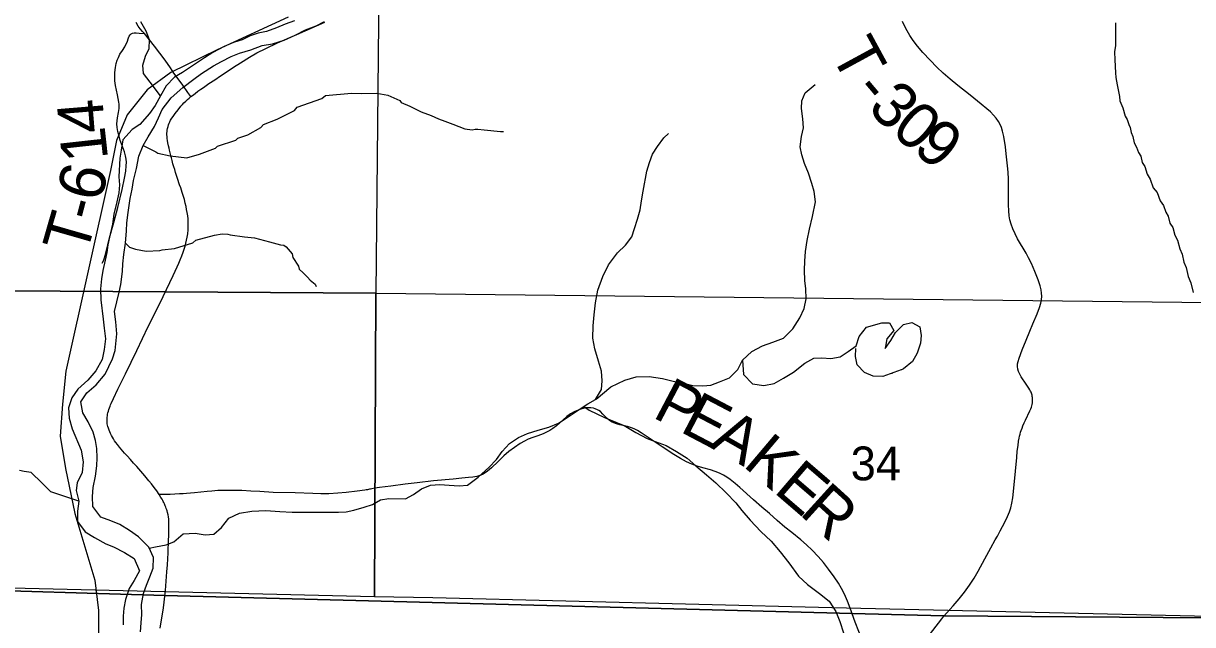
# Model space of a CAD drawing. Extents: x 0 to 34, y -8.9 to 22.
# Drawn here: x 24.652 to 26.101, y 15.928 to 16.673 of the extents above; entities that cross this region are included whole.
import ezdxf

# ---------------------------------------------------------------- set-up
doc = ezdxf.new("R2010")
doc.units = 0
for name, color, linetype in [('GM_X_Corporation', 7, 'Continuous'), ('GM_X_Major_River', 7, 'Continuous'), ('GM_X_Minor_River', 7, 'Continuous'), ('GM_X_Rail_Line', 7, 'Continuous'), ('GM_X_Section_Text', 7, 'Continuous'), ('GM_X_State_Route', 7, 'Continuous'), ('GM_X_Township_Road', 7, 'Continuous'), ('GM_X_Township_Road_Text', 7, 'Continuous')]:
    doc.layers.add(name, color=color, linetype=linetype)

msp = doc.modelspace()

# ---------------------------------------------------------------- linework, layer by layer
at = {"layer": 'GM_X_Corporation'}
for points in [[(23.7167, 19.34), (23.7167, 15.9913), (24.0651, 15.9828), (24.2771, 15.9807), (24.8268, 15.964), (25.6785, 15.9418), (25.7922, 15.939), (26.1186, 15.9366), (26.135, 17.3055), (26.1361, 17.3278), (26.1391, 17.8847), (26.1399, 18.3037), (25.7381, 18.312), (25.2083, 18.3108), (25.1045, 18.3117), (25.1124, 18.5932), (25.1216, 18.6194), (25.125, 18.6354), (25.1229, 18.6966), (25.1136, 18.8385), (25.1068, 18.8675), (25.1066, 19.3232), (25.0504, 19.3237), (24.5181, 19.3295)], [(24.0671, 17.3595), (25.0983, 17.3466), (25.0882, 16.3389), (24.0445, 16.3452)], [(23.7167, 15.9913), (23.7167, 14.6), (28.1739, 14.6), (28.1809, 15.2987), (28.1918, 16.1509), (28.1846, 16.3341), (28.1817, 16.6637), (28.1928, 16.8054), (28.1882, 17.3108), (27.911, 17.3104), (27.4798, 17.3159), (27.0561, 17.3117), (26.7292, 17.3169), (26.394, 17.3229), (26.1361, 17.3278), (26.135, 17.3055), (26.1186, 15.9366), (25.7922, 15.939), (25.6785, 15.9418), (24.8268, 15.964), (24.2771, 15.9807), (24.0651, 15.9828)], [(24.0445, 16.3452), (25.0882, 16.3389), (25.0869, 15.9626), (24.1515, 15.9848), (24.0358, 15.9873)], [(25.0882, 16.3389), (26.1244, 16.3272), (26.121, 15.938), (25.6533, 15.9488), (25.159, 15.9613), (25.0869, 15.9626)]]:
    msp.add_lwpolyline(points, close=True, dxfattribs=at)
at = {"layer": 'GM_X_Major_River'}
for points in [[(24.9876, 16.6763), (24.9759, 16.672), (24.9654, 16.6673), (24.9529, 16.663), (24.9427, 16.6609), (24.9325, 16.6574), (24.9227, 16.6527), (24.9118, 16.6491), (24.9005, 16.6444), (24.8862, 16.637), (24.876, 16.6305), (24.8636, 16.6219), (24.8486, 16.6123), (24.8388, 16.6064), (24.8284, 16.5957), (24.8217, 16.5834), (24.815, 16.5712), (24.808, 16.5613), (24.796, 16.5478), (24.7862, 16.5416), (24.7747, 16.5289), (24.7726, 16.516), (24.7712, 16.5058), (24.77, 16.483), (24.7709, 16.4728), (24.7699, 16.4629), (24.7674, 16.4519), (24.7638, 16.4366), (24.7621, 16.4241), (24.7592, 16.4119), (24.7563, 16.3986), (24.755, 16.3891), (24.7528, 16.3796), (24.7499, 16.367), (24.7486, 16.3564), (24.7472, 16.3442), (24.7474, 16.3306), (24.7504, 16.3067), (24.7517, 16.2954), (24.7534, 16.2821), (24.7517, 16.2688), (24.7492, 16.2567), (24.7414, 16.2425), (24.7313, 16.231), (24.719, 16.2198), (24.7115, 16.2091), (24.7075, 16.1965), (24.7085, 16.1837), (24.712, 16.1708), (24.723, 16.1444), (24.7255, 16.1296), (24.7245, 16.1167), (24.7183, 16.1038), (24.7169, 16.0943), (24.7205, 16.081), (24.7187, 16.0685), (24.7185, 16.056), (24.7282, 16.0432), (24.7397, 16.0362), (24.7538, 16.0284), (24.7633, 16.0243), (24.7767, 16.0173), (24.7889, 16.0099), (24.7956, 15.9948), (24.7889, 15.9826), (24.7826, 15.973), (24.7782, 15.9593), (24.7761, 15.9486), (24.7751, 15.9388), (24.7752, 15.9278)], [(24.7966, 15.9193), (24.7976, 15.9304), (24.7982, 15.9406), (24.798, 15.9531), (24.8005, 15.9668), (24.8042, 15.9771), (24.8082, 15.9874), (24.8126, 15.9981), (24.8128, 16.0114), (24.8069, 16.0242), (24.7942, 16.0369), (24.7831, 16.0447), (24.7713, 16.0521), (24.7599, 16.0565), (24.7477, 16.0613), (24.7376, 16.0744), (24.7374, 16.087), (24.7381, 16.098), (24.7409, 16.112), (24.7426, 16.125), (24.7429, 16.1348), (24.7427, 16.1462), (24.7411, 16.1564), (24.7379, 16.1666), (24.732, 16.1794), (24.7251, 16.1903), (24.7226, 16.204), (24.7304, 16.2154), (24.7416, 16.2251), (24.7528, 16.2385), (24.7621, 16.2572), (24.7653, 16.2679), (24.7673, 16.2884), (24.766, 16.3032), (24.7647, 16.316), (24.7675, 16.3282), (24.7704, 16.34), (24.7722, 16.3495), (24.7746, 16.3655), (24.7749, 16.375), (24.7762, 16.3867), (24.7783, 16.4008), (24.7792, 16.416), (24.7799, 16.4259), (24.7816, 16.4388), (24.784, 16.4559), (24.7865, 16.4677), (24.7882, 16.4783), (24.7918, 16.4931), (24.7947, 16.5084), (24.8002, 16.5217), (24.8061, 16.5324), (24.8139, 16.5454), (24.819, 16.5561), (24.8234, 16.5664), (24.8346, 16.5806), (24.8492, 16.5937), (24.8627, 16.6037), (24.8725, 16.6107), (24.8872, 16.6204), (24.8969, 16.6258), (24.909, 16.632), (24.9196, 16.636), (24.9335, 16.6403), (24.9475, 16.6455), (24.9603, 16.6475), (24.9747, 16.6523), (24.9882, 16.6585), (25.0014, 16.6651), (25.0143, 16.6699)], [(25.0143, 16.6699), (25.0248, 16.6753)]]:
    msp.add_lwpolyline(points, dxfattribs=at)
at = {"layer": 'GM_X_Minor_River'}
for points in [[(24.8217, 16.5834), (24.8086, 16.6001), (24.8006, 16.6107), (24.7998, 16.6213), (24.8029, 16.6322), (24.8074, 16.642), (24.8078, 16.6526), (24.8039, 16.6634), (24.7971, 16.675)], [(26.0048, 16.6735), (26.005, 16.6663), (26.0049, 16.6454), (26.0039, 16.6378), (26.0041, 16.6279), (26.0048, 16.6116), (26.0052, 16.6059), (26.0069, 16.5968), (26.0098, 16.5824), (26.0103, 16.5771), (26.0142, 16.5684), (26.0171, 16.5582), (26.0194, 16.5537), (26.0214, 16.5476), (26.023, 16.5438), (26.0243, 16.5378), (26.0266, 16.5329), (26.0283, 16.5249), (26.031, 16.5197), (26.0334, 16.5129), (26.0362, 16.5083), (26.0382, 16.5008), (26.0413, 16.4955), (26.0441, 16.486), (26.048, 16.48), (26.0516, 16.4694), (26.0567, 16.4635), (26.0603, 16.4532), (26.0646, 16.4472), (26.0674, 16.4389), (26.0701, 16.434), (26.0725, 16.4253), (26.076, 16.4201), (26.0785, 16.4106), (26.0816, 16.4046), (26.0845, 16.3936), (26.0876, 16.3872), (26.0897, 16.377), (26.0925, 16.3706), (26.0949, 16.3592), (26.0985, 16.3516), (26.1013, 16.3395)], [(25.3613, 16.2075), (25.3795, 16.2228), (25.397, 16.231), (25.4111, 16.235), (25.4271, 16.2356), (25.4434, 16.2331), (25.457, 16.2299), (25.4695, 16.2272), (25.4813, 16.2244), (25.4934, 16.2239), (25.5037, 16.2249), (25.5143, 16.2289), (25.5265, 16.2338), (25.5369, 16.2443), (25.5427, 16.2556), (25.5542, 16.2665), (25.5676, 16.2735), (25.5802, 16.278), (25.5935, 16.2831), (25.605, 16.2944), (25.6139, 16.308), (25.6193, 16.3197), (25.6217, 16.3318), (25.6211, 16.344), (25.6201, 16.3546), (25.6195, 16.3671), (25.62, 16.3785), (25.6209, 16.3903), (25.6229, 16.4039), (25.6257, 16.4179), (25.6293, 16.4339), (25.6333, 16.4517), (25.6315, 16.4646), (25.6286, 16.4745), (25.6246, 16.4874), (25.6194, 16.4993), (25.6164, 16.5103), (25.6143, 16.5202), (25.6159, 16.5327), (25.6183, 16.5437), (25.6177, 16.5547), (25.6159, 16.5676), (25.6164, 16.5771), (25.6203, 16.5869), (25.6326, 16.5971)], [(24.8002, 16.5217), (24.8156, 16.5138), (24.8183, 16.5123), (24.8335, 16.5087), (24.8541, 16.5064), (24.8699, 16.5108), (24.8895, 16.5184), (24.8922, 16.5207), (24.9148, 16.5282), (24.9174, 16.5309), (24.9299, 16.5349), (24.946, 16.5439), (24.949, 16.5478), (24.966, 16.5545), (24.9874, 16.5651), (24.9908, 16.5693), (25.0213, 16.5801), (25.0258, 16.5836), (25.0584, 16.5864), (25.0702, 16.5862), (25.0896, 16.5865), (25.1033, 16.584), (25.1182, 16.5774), (25.1198, 16.5748), (25.1305, 16.5704), (25.1446, 16.5634), (25.1569, 16.5587), (25.166, 16.5546), (25.1737, 16.5517), (25.1836, 16.5481), (25.1985, 16.5422), (25.2076, 16.5412), (25.2114, 16.542), (25.2148, 16.5421), (25.2225, 16.5411), (25.243, 16.5391), (25.2464, 16.5392)], [(24.8074, 16.0228), (24.8154, 16.0243), (24.8284, 16.0268), (24.8379, 16.0305), (24.8498, 16.0406), (24.8646, 16.0416), (24.8767, 16.0392), (24.8874, 16.0402), (24.8973, 16.0484), (24.9062, 16.0601), (24.9195, 16.066), (24.9347, 16.0685), (24.9522, 16.0695), (24.9693, 16.0682), (24.9845, 16.0676), (25, 16.0675), (25.0175, 16.0676), (25.0422, 16.0674), (25.0517, 16.068), (25.0612, 16.0698), (25.0741, 16.0735), (25.0844, 16.0768), (25.094, 16.0828), (25.1046, 16.0842), (25.1251, 16.0839), (25.1351, 16.0895), (25.145, 16.0963), (25.1561, 16.1007), (25.1678, 16.1017), (25.1792, 16.1008), (25.1917, 16.0999), (25.202, 16.101), (25.215, 16.1107), (25.2284, 16.1227), (25.2377, 16.1328), (25.245, 16.1426), (25.2542, 16.1524), (25.2653, 16.1599), (25.2764, 16.1651), (25.2897, 16.1691), (25.3026, 16.1728), (25.3148, 16.1776), (25.329, 16.1873), (25.3405, 16.1948), (25.3512, 16.2015), (25.3607, 16.2071), (25.3681, 16.2195), (25.3689, 16.2301), (25.3679, 16.2423), (25.3643, 16.2545), (25.3599, 16.2697), (25.3573, 16.283), (25.3575, 16.2982), (25.3588, 16.3119), (25.3605, 16.3267), (25.3633, 16.3426), (25.3696, 16.3592), (25.3766, 16.3739), (25.3877, 16.3886), (25.3977, 16.3984), (25.4054, 16.4086), (25.4089, 16.4188), (25.4128, 16.4305), (25.416, 16.4419), (25.4176, 16.4532), (25.4197, 16.465), (25.4241, 16.49), (25.4276, 16.5006), (25.4312, 16.5108), (25.4374, 16.5206), (25.4454, 16.5311), (25.4512, 16.5364)], [(24.7783, 16.4008), (24.7831, 16.3958), (24.7907, 16.3933), (24.8037, 16.3909), (24.8207, 16.3915), (24.8234, 16.3923), (24.8389, 16.3941), (24.8616, 16.4013), (24.8653, 16.4044), (24.8884, 16.4104), (24.8978, 16.4121), (24.905, 16.4118), (24.9077, 16.4111), (24.9256, 16.4087), (24.9382, 16.4074), (24.9565, 16.4024), (24.9702, 16.3988), (24.9744, 16.3981), (24.9774, 16.3963), (24.9848, 16.3873), (24.9856, 16.3831), (24.9927, 16.3722), (24.9935, 16.3684), (24.9985, 16.3639), (25.0035, 16.3587), (25.007, 16.3549), (25.0132, 16.3497), (25.0144, 16.3471)], [(25.5427, 16.2556), (25.544, 16.2381), (25.5553, 16.2266), (25.569, 16.2242), (25.5819, 16.2267), (25.5937, 16.2334), (25.606, 16.2409), (25.6198, 16.2521), (25.6312, 16.2581), (25.6411, 16.2587), (25.6521, 16.2578), (25.6639, 16.26), (25.6738, 16.2663), (25.6834, 16.2734), (25.6873, 16.2852), (25.6962, 16.2968), (25.7152, 16.3019), (25.7247, 16.3022), (25.7303, 16.2923), (25.7214, 16.2821), (25.7194, 16.2704), (25.7267, 16.2802), (25.7325, 16.29), (25.7421, 16.2998), (25.7524, 16.3023), (25.7626, 16.2969), (25.764, 16.2862), (25.7632, 16.2768), (25.7592, 16.2646), (25.7534, 16.2541), (25.7423, 16.2451), (25.7396, 16.2439)], [(25.7393, 16.2438), (25.7168, 16.2355), (25.7046, 16.236), (25.694, 16.2403), (25.6847, 16.2499), (25.6829, 16.2602), (25.683, 16.27), (25.6833, 16.27)], [(25.7282, 16.2389), (25.7284, 16.2391)], [(25.3461, 16.1982), (25.3526, 16.1939), (25.3719, 16.1849), (25.3858, 16.1791), (25.3961, 16.1748), (25.4104, 16.1663), (25.4247, 16.1585), (25.4346, 16.155), (25.4482, 16.1499), (25.461, 16.1426), (25.4742, 16.1345), (25.4851, 16.1249), (25.4983, 16.1137), (25.5096, 16.1037), (25.5227, 16.0914), (25.5344, 16.0791), (25.5419, 16.0696), (25.5524, 16.0577), (25.5655, 16.0435), (25.5783, 16.0316), (25.5895, 16.0182), (25.6, 16.0048), (25.612, 15.9883), (25.6233, 15.978), (25.6383, 15.9668), (25.65, 15.9572), (25.6582, 15.9442), (25.6634, 15.932), (25.6678, 15.9179)], [(24.7205, 16.081), (24.6858, 16.0926), (24.6746, 16.1039), (24.6611, 16.1166), (24.6524, 16.1179), (24.6467, 16.119)]]:
    msp.add_lwpolyline(points, dxfattribs=at)
at = {"layer": 'GM_X_Rail_Line'}
msp.add_lwpolyline([(24.9797, 16.6807), (24.8918, 16.6401), (24.8343, 16.612), (24.8048, 16.5906), (24.7804, 16.5596), (24.7671, 16.5278), (24.7597, 16.4909), (24.7044, 16.242), (24.7, 16.2014), (24.697, 16.1616), (24.7037, 16.1217), (24.7155, 16.0656), (24.7401, 15.9831), (24.7447, 15.9458), (24.7445, 15.9179)], dxfattribs=at)
at = {"layer": 'GM_X_State_Route'}
for points in [[(24.827, 15.9635), (24.8277, 15.9704), (24.8285, 15.9818), (24.8294, 15.9937), (24.83, 16.0023), (24.8305, 16.0098), (24.8309, 16.0171), (24.8311, 16.0228), (24.8314, 16.0278), (24.8315, 16.0322), (24.8318, 16.0385), (24.832, 16.0447), (24.832, 16.0484), (24.832, 16.0516), (24.8318, 16.056), (24.8317, 16.0586), (24.8314, 16.0616), (24.8309, 16.0642), (24.8303, 16.0669), (24.8297, 16.069), (24.8293, 16.0705), (24.8287, 16.0721), (24.8281, 16.0738), (24.8275, 16.0751), (24.8269, 16.0766), (24.8264, 16.0778), (24.8257, 16.0794), (24.825, 16.0807), (24.8244, 16.0819), (24.8234, 16.0836), (24.8221, 16.0856), (24.8198, 16.0893), (24.8169, 16.0938), (24.8138, 16.0981), (24.8103, 16.1027), (24.8072, 16.1064), (24.802, 16.1125), (24.7971, 16.1183), (24.7922, 16.1239), (24.7882, 16.1283), (24.7842, 16.1327), (24.7801, 16.1371), (24.777, 16.1406), (24.7747, 16.1432), (24.7705, 16.1481), (24.7681, 16.1511), (24.766, 16.1538), (24.7645, 16.1558), (24.7631, 16.1581), (24.7619, 16.1603), (24.7606, 16.1626), (24.7596, 16.1648), (24.7586, 16.167), (24.7578, 16.169), (24.757, 16.1713), (24.7564, 16.1734), (24.7559, 16.1752), (24.7556, 16.177), (24.7554, 16.1791), (24.7553, 16.181), (24.7553, 16.1828), (24.7554, 16.1848), (24.7557, 16.187), (24.756, 16.1888), (24.7564, 16.1905), (24.7569, 16.1924), (24.7576, 16.1947), (24.7583, 16.1968), (24.759, 16.1987), (24.7596, 16.2005), (24.7603, 16.2022), (24.7631, 16.2081), (24.7687, 16.2199), (24.778, 16.2388), (24.7921, 16.2679), (24.8064, 16.2975), (24.8147, 16.3142), (24.8248, 16.3348), (24.8373, 16.3606), (24.8422, 16.3713), (24.8441, 16.3758), (24.8459, 16.38), (24.8481, 16.3852), (24.8496, 16.3894), (24.851, 16.3934), (24.852, 16.397), (24.8531, 16.4008), (24.8538, 16.4043), (24.8546, 16.4081), (24.8552, 16.4121), (24.8557, 16.4173), (24.8559, 16.4223), (24.8558, 16.4273), (24.8557, 16.4307), (24.8553, 16.4346), (24.8546, 16.4386), (24.8539, 16.4426), (24.8532, 16.4462), (24.8522, 16.4502), (24.8511, 16.4546), (24.8499, 16.4585), (24.8485, 16.4633), (24.8466, 16.4691), (24.8452, 16.4731), (24.8426, 16.4808), (24.8414, 16.4846), (24.8402, 16.4882), (24.8392, 16.4918), (24.8381, 16.4953), (24.837, 16.499), (24.8358, 16.5033), (24.835, 16.5064), (24.8342, 16.5092), (24.8334, 16.5128), (24.8327, 16.5158), (24.8321, 16.5184), (24.8315, 16.5211), (24.8307, 16.5248), (24.8302, 16.528), (24.8298, 16.5304), (24.8296, 16.5328), (24.8294, 16.5348), (24.8295, 16.5369), (24.8296, 16.5389), (24.8299, 16.5407), (24.8302, 16.5428), (24.8309, 16.5452), (24.8315, 16.5474), (24.8323, 16.5495), (24.8332, 16.5512), (24.8341, 16.5529), (24.8357, 16.5554), (24.8371, 16.5576), (24.8396, 16.5612), (24.8433, 16.5659), (24.8469, 16.5703), (24.8486, 16.5723), (24.8506, 16.5744), (24.8528, 16.5766), (24.8549, 16.5786), (24.8571, 16.5804), (24.8592, 16.5822), (24.8613, 16.5838), (24.8643, 16.5861), (24.8678, 16.5888), (24.8715, 16.5913), (24.8749, 16.5937), (24.8815, 16.5983), (24.8887, 16.6031), (24.896, 16.6079), (24.9068, 16.6152), (24.912, 16.6186), (24.9208, 16.6243), (24.9319, 16.6311), (24.941, 16.6363), (24.952, 16.642), (24.9666, 16.6489), (24.9905, 16.6594), (25.0252, 16.6745)], [(24.8211, 15.9237), (24.8225, 15.9316), (24.8241, 15.9412), (24.8251, 15.9488), (24.8261, 15.9558), (24.827, 15.9635)]]:
    msp.add_lwpolyline(points, dxfattribs=at)
at = {"layer": 'GM_X_Township_Road'}
for points in [[(24.8016, 16.6603), (24.7992, 16.6628), (24.7964, 16.6661), (24.7939, 16.6697), (24.7915, 16.674)], [(25.7924, 15.9385), (25.7955, 15.9422), (25.8037, 15.9514), (25.8113, 15.9602), (25.8178, 15.9684), (25.824, 15.977), (25.8298, 15.9858), (25.8348, 15.9943), (25.843, 16.0097), (25.8504, 16.0233), (25.8559, 16.033), (25.8586, 16.0378), (25.8622, 16.0443), (25.868, 16.0552), (25.8712, 16.0619), (25.8736, 16.0677), (25.8753, 16.073), (25.8765, 16.0784), (25.8776, 16.0852), (25.8794, 16.1012), (25.8809, 16.1182), (25.8825, 16.1352), (25.8833, 16.143), (25.8842, 16.1502), (25.8849, 16.1553), (25.8856, 16.1592), (25.8861, 16.1616), (25.8867, 16.164), (25.8873, 16.1665), (25.8881, 16.1688), (25.8891, 16.1716), (25.8903, 16.1746), (25.8917, 16.178), (25.8933, 16.1813), (25.899, 16.1929), (25.9001, 16.1954), (25.9008, 16.1975), (25.9013, 16.1993), (25.9018, 16.201), (25.902, 16.203), (25.9022, 16.2047), (25.9023, 16.2063), (25.9022, 16.2078), (25.902, 16.2094), (25.9018, 16.2109), (25.9015, 16.2123), (25.9011, 16.2138), (25.9003, 16.2159), (25.8997, 16.2173), (25.8988, 16.2191), (25.8977, 16.2211), (25.8944, 16.2262), (25.8881, 16.2353), (25.8863, 16.2385), (25.8849, 16.2419), (25.8841, 16.2448), (25.8836, 16.2479), (25.8837, 16.251), (25.8842, 16.254), (25.8855, 16.2582), (25.8893, 16.2687), (25.8941, 16.2805), (25.8987, 16.2916), (25.9025, 16.3008), (25.9079, 16.3133), (25.9107, 16.3209), (25.9123, 16.3263), (25.9132, 16.3305), (25.9135, 16.3349), (25.9134, 16.3386), (25.9127, 16.3429), (25.9115, 16.3477), (25.909, 16.3553), (25.905, 16.3657), (25.9009, 16.3753), (25.8973, 16.3825), (25.8941, 16.3885), (25.8837, 16.4062), (25.8805, 16.4122), (25.8778, 16.4185), (25.8757, 16.4244), (25.8742, 16.4297), (25.8733, 16.4346), (25.8726, 16.4408), (25.8723, 16.4482), (25.8725, 16.4619), (25.8723, 16.4799), (25.8719, 16.4886), (25.8712, 16.4966), (25.8696, 16.5114), (25.8685, 16.52), (25.8665, 16.5329), (25.8651, 16.5396), (25.8638, 16.5438), (25.8621, 16.5478), (25.86, 16.5515), (25.8571, 16.5556), (25.8539, 16.5594), (25.8499, 16.5632), (25.8338, 16.5768), (25.8247, 16.5842), (25.8097, 16.5962), (25.8, 16.6038), (25.7915, 16.6111), (25.7834, 16.6188), (25.7751, 16.6272), (25.7664, 16.6368), (25.7596, 16.6448), (25.7543, 16.6517), (25.7501, 16.6578), (25.7466, 16.6637), (25.7435, 16.6698), (25.741, 16.6755)], [(24.7494, 16.3761), (24.7507, 16.3789), (24.752, 16.3824), (24.7537, 16.3884), (24.7585, 16.4071), (24.7638, 16.4262), (24.7688, 16.4449), (24.7739, 16.4673), (24.7769, 16.4813), (24.7784, 16.4898), (24.7791, 16.4966), (24.7792, 16.501), (24.7789, 16.5047), (24.7781, 16.509), (24.7767, 16.5138), (24.773, 16.5236), (24.7716, 16.5278), (24.7701, 16.5331), (24.7687, 16.5392), (24.7679, 16.5441), (24.7676, 16.5484), (24.7677, 16.5522), (24.7681, 16.5559), (24.7694, 16.5626), (24.7702, 16.5675), (24.7704, 16.5706), (24.7701, 16.573), (24.7697, 16.5754), (24.7681, 16.5846), (24.7657, 16.5961), (24.765, 16.6017), (24.7648, 16.6066), (24.765, 16.6122), (24.7657, 16.6184), (24.7666, 16.6233), (24.7679, 16.6274), (24.7693, 16.6309), (24.7713, 16.6347), (24.7743, 16.6394), (24.7774, 16.6441), (24.7787, 16.6469), (24.78, 16.6498), (24.7818, 16.6551), (24.7828, 16.6573), (24.7839, 16.6588), (24.7853, 16.66), (24.787, 16.6607), (24.7888, 16.6612), (24.7912, 16.6613), (24.7949, 16.6609), (24.8016, 16.6603)], [(24.8592, 16.5822), (24.8555, 16.5873), (24.849, 16.5964), (24.8422, 16.606), (24.8382, 16.6115), (24.8337, 16.6181), (24.8271, 16.6272), (24.8141, 16.6446), (24.8016, 16.6603)], [(25.6787, 15.9413), (25.6773, 15.9451), (25.6727, 15.9573), (25.669, 15.9658), (25.6653, 15.973), (25.6615, 15.9794), (25.6564, 15.9872), (25.6495, 15.9967), (25.643, 16.005), (25.6365, 16.0125), (25.6292, 16.0202), (25.6221, 16.0271), (25.6151, 16.0332), (25.6039, 16.0421), (25.5951, 16.049), (25.5857, 16.057), (25.576, 16.0657), (25.5667, 16.0738), (25.5564, 16.0827), (25.5393, 16.0981), (25.5337, 16.103), (25.5275, 16.1081), (25.5234, 16.1109), (25.5191, 16.1134), (25.5141, 16.1158), (25.5089, 16.1179), (25.503, 16.1197), (25.4935, 16.1223), (25.4864, 16.1245), (25.48, 16.1269), (25.4732, 16.13), (25.4661, 16.1338), (25.4576, 16.1389), (25.443, 16.1484), (25.4269, 16.159), (25.4172, 16.1657), (25.4125, 16.1687), (25.4086, 16.1706), (25.4052, 16.1719), (25.4004, 16.1734), (25.3907, 16.1755), (25.3865, 16.1767), (25.3831, 16.178), (25.3803, 16.1795), (25.3778, 16.1812), (25.375, 16.1836), (25.3698, 16.189), (25.3667, 16.1921), (25.3647, 16.1935), (25.3631, 16.1943), (25.3603, 16.1955), (25.358, 16.1963), (25.3549, 16.1968), (25.3518, 16.1969), (25.3481, 16.1965), (25.3438, 16.1956), (25.3391, 16.194), (25.334, 16.1917), (25.3297, 16.1892), (25.3252, 16.1859), (25.32, 16.1815), (25.3121, 16.1745), (25.3077, 16.1711), (25.304, 16.1687), (25.3008, 16.1669), (25.2957, 16.1645), (25.2893, 16.1622), (25.2829, 16.1599), (25.2771, 16.1577), (25.2727, 16.1556), (25.2673, 16.1525), (25.26, 16.1477), (25.2531, 16.1424), (25.2469, 16.1372), (25.2398, 16.1303), (25.2318, 16.1225), (25.2266, 16.1181), (25.2238, 16.116), (25.2206, 16.1142), (25.2172, 16.1128), (25.2136, 16.1118), (25.2087, 16.1109), (25.2032, 16.1102), (25.1951, 16.1094), (25.184, 16.1084), (25.1599, 16.1061), (25.1395, 16.1039), (25.1247, 16.1021), (25.1069, 16.0998), (25.0927, 16.0979), (25.0873, 16.097), (25.0835, 16.0965), (25.0818, 16.0961), (25.0805, 16.0959), (25.0782, 16.0953), (25.0765, 16.095), (25.0749, 16.0947), (25.0653, 16.0933), (25.0517, 16.0918), (25.0412, 16.0909), (25.03, 16.0903), (25.0201, 16.0901), (25.0102, 16.0904), (24.9885, 16.0913), (24.9613, 16.092), (24.9445, 16.0929), (24.9333, 16.0934), (24.9222, 16.0941), (24.9135, 16.0943), (24.9005, 16.0943), (24.8955, 16.0943), (24.8924, 16.0941), (24.885, 16.0936), (24.8793, 16.093), (24.8716, 16.0921), (24.8635, 16.0913), (24.8587, 16.0909), (24.8539, 16.0906), (24.8497, 16.0903), (24.8452, 16.09), (24.8391, 16.0897), (24.8335, 16.0895), (24.8268, 16.0894), (24.8198, 16.0893)], [(25.7251, 15.8552), (25.7242, 15.8566), (25.7189, 15.8635), (25.716, 15.8676), (25.7139, 15.8706), (25.7125, 15.8727), (25.7085, 15.879), (25.7031, 15.888), (25.6959, 15.9011), (25.6911, 15.9105), (25.687, 15.9196), (25.6824, 15.9311), (25.6787, 15.9413)], [(25.7251, 15.8552), (25.7305, 15.8617), (25.7397, 15.8727), (25.7496, 15.8844), (25.7633, 15.9012), (25.7896, 15.9351), (25.7924, 15.9385)]]:
    msp.add_lwpolyline(points, dxfattribs=at)

# ---------------------------------------------------------------- texts
at = {"layer": 'GM_X_Section_Text'}
msp.add_text('34', height=0.04186, rotation=0, dxfattribs=at).set_placement((25.6768, 16.1069))
at = {"layer": 'GM_X_Township_Road_Text'}
for s, rotation, p in [('T', 298.5126, (25.6509, 16.6361)), ('-', 310.1844, (25.6783, 16.5884)), ('3', 314.2996, (25.6964, 16.5673)), ('4', 94.6626, (24.7529, 16.5388)), ('0', 319.8162, (25.7252, 16.5381)), ('9', 321.2792, (25.7522, 16.5153)), ('1', 96.2779, (24.7567, 16.5047)), ('6', 77.2043, (24.7478, 16.4504)), ('-', 75.2058, (24.7414, 16.4259)), ('T', 73.9521, (24.7293, 16.3838)), ('P', 332.2959, (25.4297, 16.1858)), ('E', 332.2943, (25.4636, 16.168)), ('A', 330.2777, (25.5008, 16.1485)), ('K', 319.7579, (25.5419, 16.1253)), ('E', 319.3132, (25.58, 16.093)), ('R', 317.7775, (25.6119, 16.0656))]:
    msp.add_text(s, height=0.0568, rotation=rotation, dxfattribs=at).set_placement(p)

doc.saveas('drawing.dxf')
